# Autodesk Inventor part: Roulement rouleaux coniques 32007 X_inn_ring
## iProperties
Created: 2000-12
Part Number: Roulement rouleaux coniques 32007 X_inn_ring
Material: Par défaut
Document SubType Name: Modélisation
Designer: Administrateur
Control State: 0
Master: False
Checked Out: False
Shininess: 20.0
Length Units: 11269
Angle Units: 11279
Time Units: 11290
Mass Units: 11283
Length Display Precision: 3
Angle Display Precision: 2
Density: 0.0
Volumn: 0.0
Area: 0.0
PropertySet Name: Model Information
Author: Administrateur
